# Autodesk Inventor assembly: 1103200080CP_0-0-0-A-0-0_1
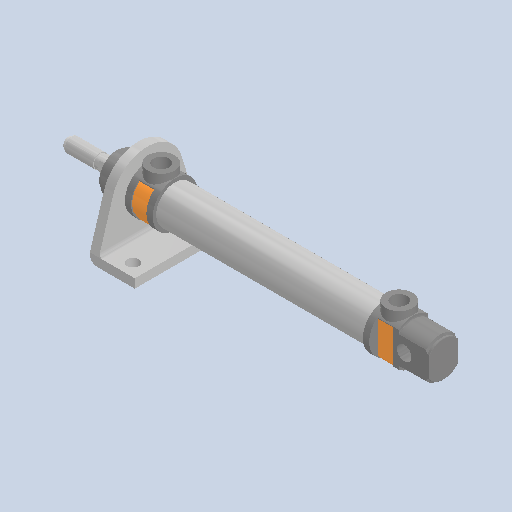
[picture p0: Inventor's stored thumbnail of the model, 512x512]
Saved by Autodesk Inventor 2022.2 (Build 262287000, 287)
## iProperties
Created: 2024-10
Part Number: 1103200080CP_0-0-0-A-0-0_1
Document SubType Name: Assembly
Designer: 18907419
Author: 18907419
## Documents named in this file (8)
- C:\Users\18907419\Desktop\automazione\nastro\1103200080CP_0-0-0-A-0-0_1.iam
- C:\Users\18907419\Desktop\automazione\nastro\ISO_6432_TP_DI20-110-HF.ipt
- C:\Users\18907419\Desktop\automazione\nastro\ISO_6432_TP_DI20-110-80-BR.ipt
- C:\Users\18907419\Desktop\automazione\nastro\ISO_6432_TP_DI20-110-HR.ipt
- C:\Users\18907419\Desktop\automazione\nastro\ISO_6432_TP_DI20-110-PR.ipt
- C:\Users\18907419\Desktop\automazione\nastro\ISO_6432_TP_DI20-11080-R.ipt
- C:\Users\18907419\Desktop\automazione\nastro\W0950200001-3_0.ipt
- C:\Users\18907419\Desktop\automazione\nastro\ISO_6432_TP_DI20-110-PF.ipt
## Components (7 placed, 7 different names)
1. ISO_6432_TP_DI20-110-HF:1
2. ISO_6432_TP_DI20-110-80-BR:1
3. ISO_6432_TP_DI20-110-HR:1
4. ISO_6432_TP_DI20-110-PR:1
5. ISO_6432_TP_DI20-11080-R:1
6. W0950200001-3_0:1
7. ISO_6432_TP_DI20-110-PF:1
